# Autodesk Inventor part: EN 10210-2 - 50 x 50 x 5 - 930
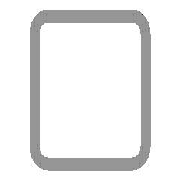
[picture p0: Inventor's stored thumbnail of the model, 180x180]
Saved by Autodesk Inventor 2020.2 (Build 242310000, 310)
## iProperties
IsCustomPart: 1
_CCFamilyMember: 16
_CCFamilyDisplayName: DIN EN 10210-2 (USAS B17.1 quadratisch) - Rohrleitung — In Klammern angegebene Größen wurden aufgehoben
_FrameMemberDoc: Frame Member File
_Version: 15.0.0
_GetPNFromCC: 1
Created: 2019-01
Part Number: EN 10210-2 - 50 x 50 x 5 - 930
Material: Stahl, weich
Description: Rohrleitung
Document SubType Name: Modeling
Standard: DIN
Designer: lutzd
Standard Revision: 2006-07
Standards Organization: DIN
Language: de-DE
Size Designation: 50 x 50 x 5
Categories: <MemberInstance><Categories><Category DisplayName="Profile" InternalName="089c4875-fa83-4c05-b084-43b9cc11f5ed" Mnemonic="GRDR"><CategoryParameter DisplayName="
Stock Number: 50 x 50 x 5
Mass: 6374.61 g
Surface Area: 3165.88 cm^2
Volume: 812.053 cm^3
Density: 7.85 g/cm^3
Appearance: Semi-Polished(8)
G_L: 930,000 mm
G_W: 50,000 mm
G_H: 50,000 mm
Dimensions: 50x50x930 mm
Mass: 6,375 kg
DocNumber: ADSK-014302
Folder: .
+C9297470-4B6D-4EE4-95F6-D3EDE89091D7+SCHNITTDETAIL1: Schnittwinkel 90,00 grd
+CABAD89D-C76E-4CE8-A451-B810AF815D31+SCHNITTDETAIL2: Schnittwinkel 90,00 grd
VLT_Material: Stahl, weich
Title: Profil-Bauteil
Author: lutzd
Revision Number: -
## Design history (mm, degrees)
node "Startebene"
node "Endebene"
sketch "Skizze"
  geometry: L1 (-25, -17.5)-(-25, 17.5); L2 (-17.5, 25)-(17.5, 25); L3 (25, 17.5)-(25, -17.5); L4 (17.5, -25)-(-17.5, -25); L5 (-15, 20)-(15, 20); L6 (20, 15)-(20, -15); L7 (15, -20)-(-15, -20); L8 (-20, -15)-(-20, 15); L9 (0, 37.175)-(0, -37.175) reference; L10 (-37.175, 0)-(37.175, 0) reference; A1 r 7.5 centre (-17.5, -17.5) between (-25, -17.5) and (-17.5, -25); A2 r 7.5 centre (-17.5, 17.5) between (-17.5, 25) and (-25, 17.5); A3 r 7.5 centre (17.5, 17.5) between (25, 17.5) and (17.5, 25); A4 r 7.5 centre (17.5, -17.5) between (17.5, -25) and (25, -17.5); A5 r 5 centre (-15, -15) between (-20, -15) and (-15, -20); A6 r 5 centre (-15, 15) between (-15, 20) and (-20, 15); A7 r 5 centre (15, 15) between (20, 15) and (15, 20); A8 r 5 centre (15, -15) between (15, -20) and (20, -15)
  constraints: 16 end point, 16 point on circle, 16 tangent, 8 centre point, 6 equal radius, 4 parallel, 2 perpendicular, 2 other
  dimensions: "d7" = 7.5 radius of A1 (= G_IR); "d10" = 50 distance between parallel lines of L2 L4 (= G_H); "d11" = 50 distance between parallel lines of L1 L3 (= G_W); "d12" = 5 distance between parallel lines of L3 L6 (= G_T); "d15" = 25 distance between parallel lines of L2 L10 (= 0.5 x d10); "d16" = 25 distance between parallel lines of L9 L3 (= 0.5 x d11); "d19" = 5 radius of A5 (= G_T); "d20" = 5 distance between parallel lines of L4 L7 (= G_T)
extrude "Körper" new body sketch "Skizze" stored distance "d3" = 930 (= G_L); taper "d4" = 0 deg
node "Driven Length"
  sketch "Sketch3"
    geometry: L1 (0, 0)-(10, 0) reference
    constraints: 2 end point, 1 horizontal
  workplane "Work Plane3"
  sketch "Sketch4"
    geometry: L1 (-2, 50)-(12, 50) reference; L2 (-2, 980)-(12, 980) reference
    dimensions: "d18" = 930 distance between parallel lines of L1 L2 (derived)
workplane "Arbeitsebene4"
feature "Trennen1"
workplane "Arbeitsebene5"
feature "Trennen2"
body "Solid1"
other parameters: "G_W" = 50 [user parameter; used in 1 equation term], "G_H" = 50 [user parameter; used in 1 equation term], "G_T" = 5 [user parameter; used in 3 equation terms], "G_IR" = 7.5 [user parameter; used in 1 equation term], "G_L" = 930 (= d18) [user parameter; used in 1 equation term], "d17" = 90 deg
